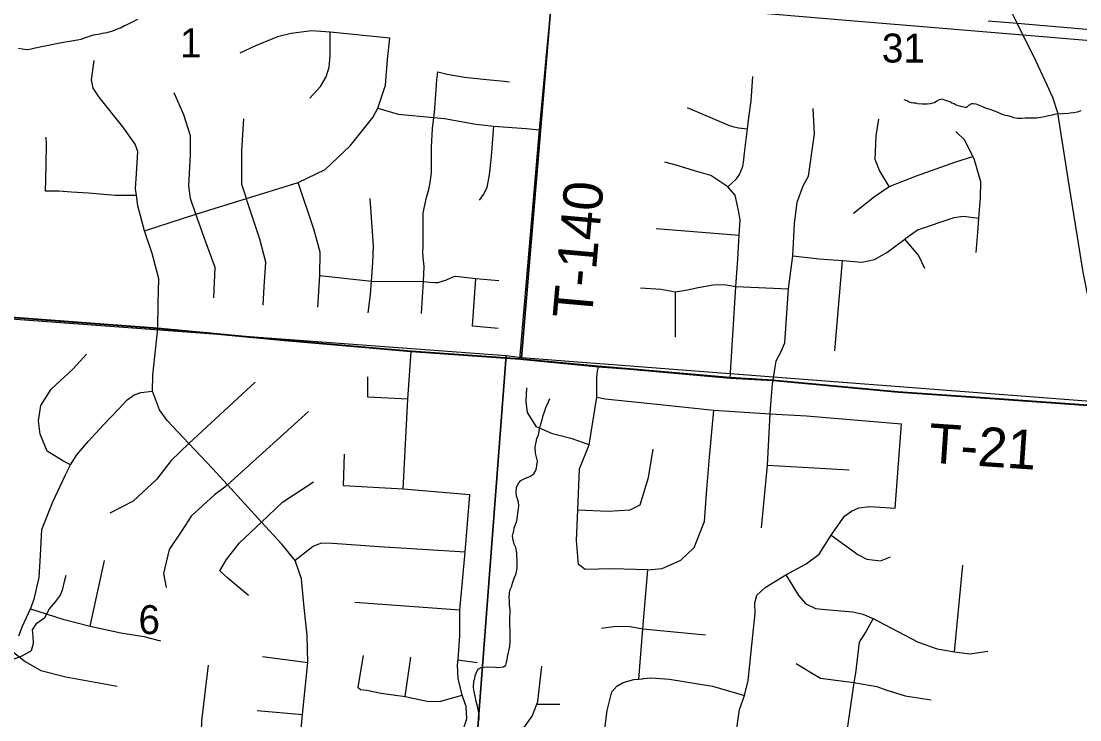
# Model space of a CAD drawing. Extents: x 0 to 34, y 0 to 22.
# Drawn here: x 5.107 to 6.638, y 19.714 to 20.725 of the extents above; entities that cross this region are included whole.
import ezdxf

# ---------------------------------------------------------------- set-up
doc = ezdxf.new("R2010")
doc.units = 0
for name, color, linetype in [('Default', 7, 'Continuous'), ('GM_X_Minor_River', 7, 'Continuous'), ('GM_X_Section', 7, 'Continuous'), ('GM_X_Section_Text', 7, 'Continuous'), ('GM_X_State_Route', 7, 'Continuous'), ('GM_X_Township_Road', 7, 'Continuous'), ('GM_X_Township_Road_Text', 7, 'Continuous')]:
    doc.layers.add(name, color=color, linetype=linetype)

msp = doc.modelspace()

# ---------------------------------------------------------------- linework, layer by layer
at = {"layer": 'Default'}
for points in [[(5.8864, 20.9), (4.8644, 20.9), (4.818, 20.3144), (5.8084, 20.2412), (5.8307, 20.238)], [(6.92, 20.9), (5.8864, 20.9), (5.8307, 20.238), (6.8362, 20.1611), (6.8487, 20.1601)]]:
    msp.add_lwpolyline(points, close=True, dxfattribs=at)
at = {"layer": 'GM_X_Minor_River'}
for points in [[(5.1029, 20.6853), (5.1082, 20.6844), (5.112, 20.6839), (5.1154, 20.6837), (5.1197, 20.6843), (5.1273, 20.686), (5.13, 20.6866), (5.1365, 20.6879), (5.1392, 20.6882), (5.1515, 20.6908), (5.158, 20.6921), (5.1607, 20.6927), (5.168, 20.694), (5.1711, 20.6946), (5.1772, 20.6955), (5.1852, 20.6971), (5.1883, 20.6978), (5.1937, 20.6987), (5.1999, 20.7012), (5.2114, 20.7046), (5.2149, 20.7052), (5.2214, 20.7065), (5.2248, 20.7071), (5.2314, 20.7084), (5.2344, 20.709), (5.2394, 20.7108), (5.2476, 20.7139), (5.2506, 20.7149), (5.2565, 20.7181), (5.2592, 20.7192), (5.2634, 20.7213), (5.2759, 20.7277)], [(6.6397, 20.595), (6.6344, 20.5928), (6.6294, 20.5918), (6.6245, 20.5915), (6.6191, 20.5908), (6.6161, 20.5909), (6.6134, 20.5906), (6.6043, 20.59), (6.6013, 20.5897), (6.5982, 20.5886), (6.5933, 20.5879), (6.5871, 20.5862), (6.5822, 20.5855), (6.5791, 20.5848), (6.5757, 20.5845), (6.5719, 20.5842), (6.5651, 20.5843), (6.5594, 20.5841), (6.5541, 20.5838), (6.548, 20.5839), (6.5427, 20.5848), (6.5397, 20.586), (6.534, 20.5876), (6.531, 20.5881), (6.5276, 20.5889), (6.5197, 20.5925), (6.514, 20.5949), (6.5087, 20.5969), (6.5035, 20.5985), (6.4982, 20.6009), (6.4933, 20.6025), (6.4884, 20.6045), (6.4842, 20.605), (6.4816, 20.605), (6.4773, 20.6024), (6.4746, 20.5995), (6.472, 20.5995), (6.4663, 20.6011), (6.4629, 20.602), (6.4595, 20.6032), (6.4565, 20.6051), (6.4531, 20.606), (6.4501, 20.6079), (6.4433, 20.6104), (6.4392, 20.6116), (6.435, 20.6109), (6.4315, 20.6091), (6.428, 20.6065), (6.4254, 20.6062), (6.4219, 20.6051), (6.4174, 20.6044), (6.4102, 20.6046), (6.4041, 20.6051), (6.4014, 20.6059), (6.398, 20.6059), (6.395, 20.6064), (6.3916, 20.6076), (6.3886, 20.6092), (6.3844, 20.6108)], [(5.7692, 19.7122), (5.7696, 19.7164), (5.7693, 19.721), (5.7687, 19.7267), (5.767, 19.734), (5.7652, 19.7405), (5.7635, 19.7485), (5.7621, 19.755), (5.7615, 19.7607), (5.762, 19.7702), (5.7632, 19.774), (5.7637, 19.7778), (5.7657, 19.783), (5.768, 19.7872), (5.7726, 19.7897), (5.7814, 19.7907), (5.7931, 19.7905), (5.7972, 19.79), (5.8048, 19.7906), (5.8082, 19.7932), (5.8091, 19.797), (5.8116, 19.8095), (5.8137, 19.8201), (5.8142, 19.8273), (5.8145, 19.8395), (5.8142, 19.844), (5.814, 19.8509), (5.8137, 19.8547), (5.8138, 19.8634), (5.8143, 19.8672), (5.8141, 19.8741), (5.8134, 19.8794), (5.8132, 19.8855), (5.8129, 19.8912), (5.8139, 19.9015), (5.8166, 19.9075), (5.8175, 19.912), (5.8203, 19.9188), (5.8226, 19.9241), (5.8239, 19.9305), (5.8244, 19.934), (5.8246, 19.9446), (5.824, 19.9515), (5.824, 19.9556), (5.8223, 19.9633), (5.8201, 19.9683), (5.818, 19.9763), (5.8177, 19.9801), (5.8186, 19.9839), (5.8194, 19.9873), (5.8202, 19.9911), (5.8219, 19.9968), (5.8239, 20.002), (5.8248, 20.0093), (5.8265, 20.0191), (5.827, 20.024), (5.8263, 20.029), (5.8256, 20.0324), (5.8234, 20.0374), (5.8228, 20.0435), (5.8237, 20.0507), (5.8269, 20.0568), (5.83, 20.0601), (5.8365, 20.0638), (5.8429, 20.0659), (5.8487, 20.07), (5.8518, 20.0756), (5.8531, 20.0821), (5.854, 20.0881), (5.8529, 20.092), (5.8512, 20.0996), (5.8506, 20.1091), (5.8519, 20.1156), (5.8531, 20.1209), (5.8551, 20.1265), (5.8564, 20.1314), (5.8572, 20.1364), (5.8584, 20.1405), (5.8597, 20.1451), (5.8609, 20.15), (5.8621, 20.1545), (5.8638, 20.1598), (5.8666, 20.1674), (5.8689, 20.1715), (5.8717, 20.1787)], [(5.0969, 19.8024), (5.1096, 19.8073), (5.122, 19.8146), (5.125, 19.8251), (5.1241, 19.8346), (5.1236, 19.8445), (5.1296, 19.8539), (5.1412, 19.8619), (5.1481, 19.8746), (5.1567, 19.8846), (5.1639, 19.8942), (5.1672, 19.9036), (5.1698, 19.9142), (5.1723, 19.9233)]]:
    msp.add_lwpolyline(points, dxfattribs=at)
at = {"layer": 'GM_X_Section'}
for points in [[(4.818, 20.3144), (5.8084, 20.2412), (5.7435, 19.3869), (4.7613, 19.5448)], [(5.8307, 20.238), (6.8362, 20.1611), (6.7522, 19.1603), (5.7435, 19.3869), (5.8084, 20.2412)]]:
    msp.add_lwpolyline(points, close=True, dxfattribs=at)
at = {"layer": 'GM_X_State_Route'}
for points in [[(5.11, 20.8251), (5.155, 20.821), (5.23, 20.8148), (5.3102, 20.8082), (5.3419, 20.8057), (5.3996, 20.8008), (5.452, 20.7964), (5.5147, 20.7914), (5.6057, 20.7839), (5.7526, 20.7719), (5.8384, 20.7648), (5.8751, 20.7612), (5.9896, 20.752), (6.1633, 20.7377), (6.3063, 20.7257), (6.3999, 20.7179), (6.5561, 20.7048), (6.7287, 20.6902)], [(6.5058, 20.7249), (6.5479, 20.7215), (6.7205, 20.7068)]]:
    msp.add_lwpolyline(points, dxfattribs=at)
at = {"layer": 'GM_X_Township_Road'}
for p, q in [((6.0257, 20.4247), (6.1457, 20.415)), ((6.284, 20.2476), (6.2949, 20.3783)), ((6.0535, 20.2678), (6.0536, 20.3331)), ((5.0725, 20.2976), (5.1625, 20.2909)), ((6.1865, 20.0824), (6.3045, 20.0756)), ((5.207, 19.8497), (5.2275, 19.9448)), ((6.4569, 19.8127), (6.4689, 19.9376)), ((5.7415, 19.8729), (5.5895, 19.8836)), ((6.0064, 19.8456), (6.0971, 19.8372)), ((5.4561, 19.8056), (5.5216, 19.7971)), ((5.6623, 19.748), (5.6706, 19.8046)), ((5.7392, 19.8009), (5.7668, 19.7971)), ((5.4485, 19.7278), (5.5137, 19.722)), ((5.8529, 19.7369), (5.8863, 19.7369))]:
    msp.add_line(p, q, dxfattribs=at)
for points in [[(5.8644, 20.6498), (5.8664, 20.6709), (5.8751, 20.7612), (5.8768, 20.7771), (5.8889, 20.8867)], [(6.591, 20.632), (6.5721, 20.6727), (6.5561, 20.7048), (6.5479, 20.7215), (6.5224, 20.7731), (6.494, 20.8479)], [(5.6404, 20.6998), (5.5538, 20.7086), (5.5268, 20.7105), (5.4975, 20.7069), (5.4778, 20.702), (5.4461, 20.6891), (5.4234, 20.6781)], [(5.5243, 20.613), (5.5398, 20.6301), (5.5481, 20.6442), (5.5527, 20.6583), (5.5541, 20.6744), (5.5538, 20.7086)], [(5.2856, 20.4215), (5.3597, 20.4456), (5.4327, 20.468), (5.5075, 20.4911), (5.5468, 20.5099), (5.583, 20.5441), (5.6159, 20.5855), (5.623, 20.599), (5.634, 20.6319), (5.637, 20.6692), (5.6404, 20.6998)], [(5.2724, 20.4825), (5.2736, 20.5039), (5.2756, 20.5361), (5.2718, 20.5467), (5.2538, 20.5716), (5.2198, 20.6145), (5.2113, 20.6279), (5.2087, 20.6398), (5.2124, 20.6677)], [(5.6859, 20.3018), (5.6888, 20.348), (5.6901, 20.3696), (5.6885, 20.3829), (5.6882, 20.3908), (5.6887, 20.3981), (5.6883, 20.4476), (5.6935, 20.4694), (5.6967, 20.4813), (5.6991, 20.4941), (5.7003, 20.5064), (5.7007, 20.5247), (5.7003, 20.5426), (5.7019, 20.5692), (5.704, 20.5851), (5.705, 20.5926), (5.7074, 20.6252), (5.7082, 20.6395), (5.7098, 20.6515)], [(5.7098, 20.6515), (5.7233, 20.6479), (5.7484, 20.6435), (5.771, 20.6411), (5.7853, 20.6399), (5.8056, 20.638), (5.8135, 20.6368)], [(5.8283, 20.2358), (5.8568, 20.5674), (5.8644, 20.6498)], [(6.129, 20.4848), (6.1419, 20.4964), (6.1459, 20.5029), (6.1507, 20.5146), (6.1523, 20.524), (6.1535, 20.5343), (6.1578, 20.569), (6.1598, 20.5854), (6.1629, 20.6096), (6.1653, 20.6447)], [(6.6786, 20.1669), (6.6661, 20.2389), (6.6547, 20.3041), (6.6433, 20.3617), (6.6228, 20.4875), (6.6064, 20.5918), (6.5991, 20.6144), (6.591, 20.632)], [(5.3859, 20.3244), (5.3875, 20.3682), (5.3736, 20.4065), (5.3597, 20.4456), (5.3521, 20.4679), (5.3495, 20.4865), (5.3518, 20.5311), (5.3521, 20.5587), (5.3423, 20.5891), (5.3281, 20.6207)], [(5.623, 20.599), (5.6523, 20.5899), (5.704, 20.5851), (5.7195, 20.5836), (5.7648, 20.5756), (5.7905, 20.5726), (5.8375, 20.5693), (5.8568, 20.5674)], [(6.0706, 20.5997), (6.1304, 20.5743), (6.1348, 20.5727), (6.1374, 20.5719), (6.1407, 20.5711), (6.1447, 20.5704), (6.1578, 20.569)], [(6.1949, 20.2058), (6.1993, 20.2332), (6.2061, 20.2457), (6.2115, 20.2593), (6.2171, 20.3376), (6.2234, 20.3851), (6.2258, 20.4313), (6.2297, 20.4626), (6.2384, 20.4863), (6.2459, 20.5006), (6.2545, 20.5617), (6.2528, 20.5981)], [(5.4568, 20.3139), (5.4586, 20.3405), (5.4608, 20.3758), (5.4522, 20.4093), (5.4339, 20.4643), (5.4327, 20.468), (5.4263, 20.4884), (5.4262, 20.5376), (5.429, 20.5834)], [(6.3625, 20.4853), (6.3488, 20.5086), (6.3421, 20.5246), (6.3436, 20.5589), (6.3477, 20.5829)], [(5.7698, 20.4655), (5.7757, 20.4739), (5.7813, 20.4842), (5.7845, 20.5025), (5.7873, 20.5287), (5.7905, 20.5726)], [(5.2737, 20.4723), (5.243, 20.4723), (5.2045, 20.4758), (5.1798, 20.4774), (5.1615, 20.4786), (5.1421, 20.4789), (5.1428, 20.4954), (5.1433, 20.5183), (5.1435, 20.546), (5.1433, 20.5568)], [(6.4882, 20.3902), (6.4907, 20.4189), (6.4924, 20.4396), (6.4949, 20.4695), (6.4953, 20.492), (6.4854, 20.5255), (6.4836, 20.5291), (6.472, 20.5527), (6.4591, 20.5649)], [(6.1326, 20.2085), (6.1409, 20.341), (6.1435, 20.3806), (6.1457, 20.415), (6.1468, 20.4371), (6.1448, 20.4507), (6.1398, 20.4727), (6.129, 20.4848), (6.1044, 20.5016), (6.081, 20.5082), (6.0545, 20.5162), (6.0382, 20.5209)], [(6.311, 20.447), (6.3413, 20.471), (6.3625, 20.4853), (6.402, 20.5007), (6.459, 20.521), (6.4836, 20.5291)], [(5.536, 20.3108), (5.5391, 20.3567), (5.5394, 20.3903), (5.5307, 20.4221), (5.5075, 20.4911)], [(5.3045, 20.2803), (5.305, 20.3167), (5.3061, 20.3521), (5.2966, 20.3887), (5.2856, 20.4215), (5.2756, 20.4574), (5.2737, 20.4723), (5.2724, 20.4825)], [(5.6087, 20.303), (5.6121, 20.3291), (5.6139, 20.3488), (5.6156, 20.3749), (5.6165, 20.3992), (5.6119, 20.4679)], [(6.2234, 20.3851), (6.2615, 20.381), (6.2949, 20.3783), (6.323, 20.3761), (6.3414, 20.3799), (6.3594, 20.3899), (6.3852, 20.4095), (6.3869, 20.4107), (6.4038, 20.4226), (6.4566, 20.4408), (6.4694, 20.4424), (6.4924, 20.4396)], [(6.4141, 20.367), (6.4048, 20.3864), (6.3852, 20.4095)], [(6.6784, 20.1674), (6.4945, 20.1803), (6.3753, 20.1886), (6.1945, 20.2053), (6.1324, 20.209), (5.9872, 20.2219), (5.9416, 20.2254), (5.8281, 20.2363), (5.6709, 20.2472), (5.6318, 20.2506), (5.4877, 20.2633), (5.3042, 20.2808), (5.0723, 20.2981), (4.8596, 20.3137), (4.6315, 20.3314), (4.446, 20.3446), (4.3596, 20.3518), (4.3531, 20.3523), (4.1078, 20.3718), (4.0283, 20.3778), (3.9475, 20.3839)], [(3.9475, 20.3839), (4.0283, 20.3778), (4.1078, 20.3718), (4.3531, 20.3523), (4.3596, 20.3518), (4.446, 20.3446), (4.6315, 20.3314), (4.8596, 20.3137), (5.0723, 20.2981), (5.3042, 20.2808), (5.4877, 20.2633), (5.6318, 20.2506), (5.6709, 20.2472), (5.8281, 20.2363), (5.9416, 20.2254), (5.9872, 20.2219), (6.1324, 20.209), (6.1945, 20.2053), (6.3753, 20.1886), (6.4945, 20.1803), (6.6784, 20.1674)], [(5.5391, 20.3567), (5.6139, 20.3488), (5.6888, 20.348), (5.6982, 20.3472), (5.7055, 20.3468), (5.7103, 20.3466), (5.7144, 20.3479), (5.7224, 20.3507), (5.7318, 20.3546), (5.735, 20.3556), (5.7394, 20.3554), (5.7645, 20.3525), (5.7981, 20.3496)], [(5.797, 20.2801), (5.7597, 20.2833), (5.7645, 20.3525)], [(6.0028, 20.3389), (6.0325, 20.3372), (6.0536, 20.3331), (6.071, 20.3361), (6.0865, 20.3394), (6.1079, 20.3432), (6.1244, 20.3437), (6.1409, 20.341), (6.2171, 20.3376)], [(5.1625, 20.2909), (5.3045, 20.2803), (5.4879, 20.2628), (5.632, 20.2501), (5.6711, 20.2466), (5.8283, 20.2358), (5.9419, 20.2248), (5.9874, 20.2213), (6.1326, 20.2085), (6.1948, 20.2048), (6.3755, 20.1881), (6.4947, 20.1797), (6.6776, 20.1669)], [(5.5061, 19.6366), (5.5137, 19.722), (5.5216, 19.7971), (5.5205, 19.8359), (5.516, 19.8816), (5.5126, 19.9182), (5.5032, 19.9445), (5.4839, 19.9682), (5.4547, 20.0002), (5.4055, 20.0539), (5.3836, 20.0778), (5.3493, 20.114), (5.318, 20.1471), (5.307, 20.1626), (5.2969, 20.1894), (5.2972, 20.2128), (5.3045, 20.2803)], [(5.6595, 20.0476), (5.6664, 20.1777), (5.6711, 20.2466)], [(5.1781, 20.083), (5.1671, 20.0886), (5.1445, 20.1027), (5.1343, 20.1271), (5.1321, 20.1468), (5.1355, 20.1686), (5.1506, 20.1924), (5.1823, 20.2219), (5.2015, 20.243)], [(6.0135, 19.9312), (5.9615, 19.9327), (5.923, 19.9316), (5.9134, 19.9389), (5.9101, 19.9735), (5.9124, 20.0177), (5.9147, 20.0771), (5.9286, 20.1117), (5.9398, 20.1807), (5.9398, 20.2091), (5.9405, 20.2189), (5.9419, 20.2248)], [(5.4455, 20.2026), (5.3493, 20.114), (5.324, 20.0894), (5.3029, 20.0615), (5.269, 20.0306), (5.235, 20.0132)], [(5.6664, 20.1777), (5.6086, 20.1808), (5.6086, 20.2104)], [(6.1778, 19.9919), (6.1865, 20.0824), (6.1906, 20.1568), (6.191, 20.1639), (6.194, 20.2001), (6.1948, 20.2048), (6.1949, 20.2058)], [(5.1038, 19.8356), (5.1091, 19.8495), (5.1204, 19.8748), (5.1257, 19.8887), (5.1332, 19.9201), (5.1347, 19.9525), (5.137, 19.9895), (5.1528, 20.0294), (5.1709, 20.0687), (5.1781, 20.083), (5.1875, 20.0973), (5.2037, 20.1167), (5.2259, 20.1407), (5.2488, 20.1642), (5.2605, 20.1769), (5.2704, 20.1844), (5.2801, 20.1875), (5.2969, 20.1894)], [(5.9286, 20.1117), (5.9042, 20.1206), (5.8758, 20.1279), (5.8524, 20.1377), (5.8395, 20.1588), (5.8373, 20.1747), (5.8384, 20.1945)], [(5.9398, 20.1807), (5.9517, 20.1784), (6.0171, 20.1716), (6.1088, 20.1621), (6.1906, 20.1568), (6.2431, 20.1536), (6.3803, 20.142)], [(5.5224, 20.1603), (5.4055, 20.0539), (5.4018, 20.0505), (5.3866, 20.0396), (5.3527, 20.0087), (5.3399, 19.9883), (5.321, 19.9604), (5.3127, 19.9257), (5.3165, 19.9053)], [(6.0135, 19.9312), (6.0341, 19.9331), (6.0611, 19.9451), (6.0804, 19.9634), (6.0953, 20.0011), (6.0986, 20.0475), (6.1025, 20.0942), (6.1088, 20.1621)], [(6.1369, 19.6331), (6.1374, 19.6595), (6.1414, 19.6955), (6.1461, 19.729), (6.1532, 19.7494), (6.1586, 19.7709), (6.1608, 19.7942), (6.1654, 19.8361), (6.1688, 19.8678), (6.1684, 19.8833), (6.171, 19.8942), (6.1832, 19.9057), (6.2133, 19.924), (6.2423, 19.9399), (6.2615, 19.9538), (6.2789, 19.9813), (6.2981, 20.0089), (6.3079, 20.016), (6.3189, 20.0209), (6.3347, 20.0228), (6.3713, 20.0202), (6.3803, 20.142)], [(5.7558, 20.0396), (5.6595, 20.0476), (5.5733, 20.0528), (5.5748, 20.0982)], [(5.9124, 20.0177), (5.956, 20.016), (5.9881, 20.0177), (6.0025, 20.0253), (6.0145, 20.0645), (6.021, 20.1058)], [(5.4357, 19.894), (5.4058, 19.919), (5.3944, 19.9294), (5.4039, 19.9462), (5.4228, 19.9699), (5.4547, 20.0002), (5.4849, 20.0289), (5.5299, 20.0585)], [(5.5922, 19.6924), (5.6711, 19.6761), (5.6951, 19.6701), (5.7113, 19.6713), (5.7264, 19.6766), (5.7396, 19.6886), (5.746, 19.6981), (5.7517, 19.7158), (5.7505, 19.7335), (5.7449, 19.7499), (5.7392, 19.7737), (5.7381, 19.7937), (5.7392, 19.8009), (5.7415, 19.8359), (5.7415, 19.8729), (5.749, 19.9566), (5.7558, 20.0396)], [(5.749, 19.9566), (5.625, 19.9645), (5.5571, 19.9692), (5.5415, 19.9697), (5.5297, 19.9651), (5.5032, 19.9445)], [(6.2789, 19.9813), (6.3174, 19.9533), (6.3305, 19.9466), (6.3502, 19.944), (6.3645, 19.95)], [(6.0004, 19.773), (6.0064, 19.8456), (6.0135, 19.9312)], [(6.2133, 19.924), (6.2216, 19.9101), (6.2314, 19.8938), (6.2419, 19.8821), (6.2559, 19.8753), (6.2706, 19.8735), (6.3102, 19.8701), (6.3245, 19.867), (6.3396, 19.8606), (6.3458, 19.8573)], [(5.1204, 19.8748), (5.1672, 19.8595), (5.207, 19.8497), (5.2512, 19.84), (5.2843, 19.8348), (5.3087, 19.8286)], [(5.9466, 19.8467), (5.967, 19.8497), (5.9877, 19.8493), (6.0064, 19.8456)], [(6.3396, 19.8606), (6.3294, 19.8425), (6.3192, 19.8267), (6.314, 19.7814), (6.3114, 19.7681), (6.301, 19.6943)], [(6.3458, 19.8573), (6.4045, 19.8263), (6.432, 19.8169), (6.4569, 19.8127), (6.4795, 19.8097), (6.5055, 19.8135)], [(5.0891, 19.8175), (5.1127, 19.7987), (5.1356, 19.7855), (5.1715, 19.7763), (5.246, 19.7628)], [(5.6016, 19.8073), (5.594, 19.7616), (5.5978, 19.7578), (5.6072, 19.7571), (5.6276, 19.7526), (5.6623, 19.748), (5.6962, 19.7405), (5.714, 19.7413), (5.7449, 19.7499)], [(5.384, 19.4945), (5.3904, 19.6258), (5.3674, 19.6816), (5.3681, 19.7126), (5.378, 19.7933)], [(5.7809, 19.586), (5.7864, 19.6332), (5.7984, 19.652), (5.823, 19.687), (5.8463, 19.7192), (5.8529, 19.7369), (5.8542, 19.7407), (5.8599, 19.7916)], [(6.228, 19.7958), (6.25, 19.7821), (6.2634, 19.7746), (6.3114, 19.7681), (6.3445, 19.7622), (6.3577, 19.7573), (6.3856, 19.749), (6.4233, 19.7429)], [(5.9405, 19.5065), (5.9406, 19.5221), (5.9376, 19.5515), (5.9364, 19.5696), (5.9394, 19.6103), (5.9437, 19.64), (5.9545, 19.7274), (5.9615, 19.7545), (5.9688, 19.763), (5.978, 19.7679), (5.9933, 19.7723), (6.0004, 19.773), (6.006, 19.7736)], [(6.006, 19.7736), (6.0071, 19.7737), (6.018, 19.7748), (6.0447, 19.7731), (6.107, 19.7629), (6.1532, 19.7494)]]:
    msp.add_lwpolyline(points, dxfattribs=at)

# ---------------------------------------------------------------- texts
at = {"layer": 'GM_X_Section_Text'}
for s, height, p in [('1', 0.0419, (5.3366, 20.6723)), ('31', 0.04186, (6.352, 20.6648)), ('6', 0.0419, (5.2766, 19.8381))]:
    msp.add_text(s, height=height, rotation=0, dxfattribs=at).set_placement(p)
at = {"layer": 'GM_X_Township_Road_Text'}
for s, rotation, p in [('T-140', 84.9329, (5.9323, 20.2927)), ('T-21', 356.1149, (6.418, 20.0864))]:
    msp.add_text(s, height=0.05682, rotation=rotation, dxfattribs=at).set_placement(p)

doc.saveas('drawing.dxf')
